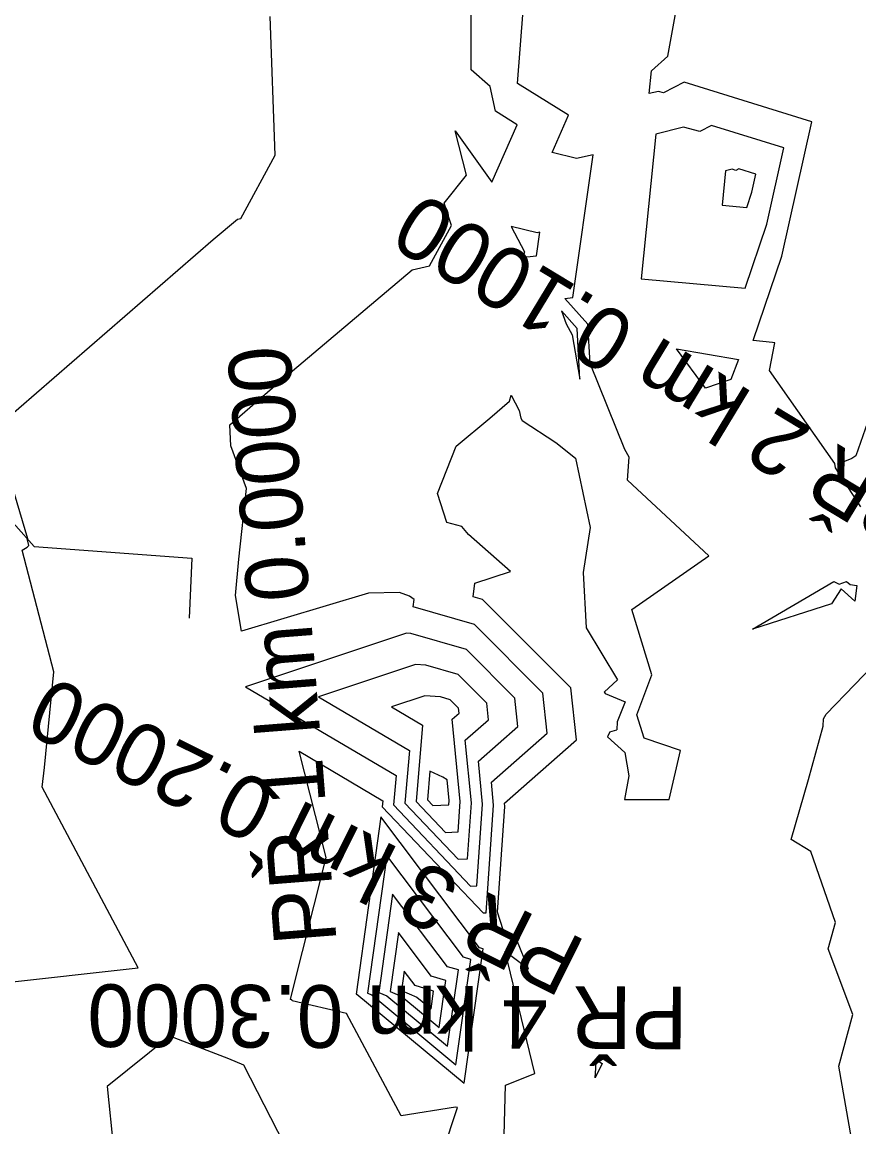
# Model space of a CAD drawing. Extents: x -549394 to -546608, y -1037055 to -1033629.
# Drawn here: x -547520.6 to -547399.4, y -1035351 to -1035190.9 of the extents above; entities that cross this region are included whole.
import ezdxf

# ---------------------------------------------------------------- set-up
doc = ezdxf.new("R2010")
doc.units = 0
for name, color, linetype in [('hlavni_vrst', 7, 'Continuous'), ('hrana_L', 7, 'Continuous'), ('norm_vrst', 7, 'Continuous'), ('x_popis_pricne_rezy_C1', 7, 'Continuous')]:
    doc.layers.add(name, color=color, linetype=linetype)

msp = doc.modelspace()

# ---------------------------------------------------------------- linework, layer by layer
at = {"layer": 'hlavni_vrst'}
for p, q in [((-547483.99, -1035210.2), (-547484.7, -1035190.12)), ((-547488.97, -1035219.38), (-547483.99, -1035210.2)), ((-547489.42, -1035219.48), (-547488.97, -1035219.38)), ((-547492.94, -1035222.45), (-547489.42, -1035219.48)), ((-547523.68, -1035249.07), (-547492.94, -1035222.45)), ((-547519.79, -1035265.79), (-547522.11, -1035257.98)), ((-547519.64, -1035266.74), (-547519.91, -1035265.75)), ((-547519.91, -1035265.75), (-547519.79, -1035265.79)), ((-547520.63, -1035267.42), (-547519.9, -1035266.99)), ((-547516.04, -1035285.05), (-547520.63, -1035267.42)), ((-547519.9, -1035266.99), (-547519.64, -1035266.74)), ((-547464.97, -1035279.47), (-547488.26, -1035287.2)), ((-547464.33, -1035279.51), (-547464.97, -1035279.47)), ((-547456.29, -1035281.82), (-547464.33, -1035279.51)), ((-547449.28, -1035288.85), (-547456.29, -1035281.82)), ((-547517.38, -1035298.89), (-547516.04, -1035285.05)), ((-547516.04, -1035285.05), (-547516.04, -1035285.05)), ((-547516.04, -1035285.05), (-547516.04, -1035285.05)), ((-547516.04, -1035285.05), (-547516.04, -1035285.05)), ((-547516.04, -1035285.05), (-547516.04, -1035285.05)), ((-547488.26, -1035287.2), (-547466.48, -1035300.08)), ((-547448.84, -1035292.96), (-547449.28, -1035288.85)), ((-547454.56, -1035297.99), (-547448.84, -1035292.96)), ((-547517.74, -1035301.73), (-547517.38, -1035298.89)), ((-547453.95, -1035304.2), (-547454.56, -1035297.99)), ((-547466.48, -1035300.08), (-547466.83, -1035304.32)), ((-547503.81, -1035327.94), (-547517.74, -1035301.73)), ((-547454.77, -1035316.04), (-547453.95, -1035304.2)), ((-547466.83, -1035304.32), (-547455.69, -1035316.08)), ((-547467.83, -1035311.63), (-547470.61, -1035331.59)), ((-547456.72, -1035326.39), (-547467.83, -1035311.63)), ((-547455.69, -1035316.08), (-547454.77, -1035316.04)), ((-547455.65, -1035326.7), (-547456.72, -1035326.39)), ((-547524.38, -1035330.2), (-547503.81, -1035327.94)), ((-547457.82, -1035341.95), (-547455.65, -1035326.7)), ((-547470.61, -1035331.59), (-547470, -1035331.85)), ((-547470, -1035331.85), (-547457.82, -1035341.95)), ((-547499.22, -1035337.83), (-547508.31, -1035345.11)), ((-547490.68, -1035341.09), (-547499.22, -1035337.83)), ((-547488.52, -1035342), (-547490.68, -1035341.09)), ((-547482.63, -1035353.51), (-547488.52, -1035342)), ((-547508.31, -1035345.11), (-547507.41, -1035354.07))]:
    msp.add_line(p, q, dxfattribs=at)
at = {"layer": 'hrana_L'}
for p, q in [((-547394.93, -1035239.52), (-547399.91, -1035253.77)), ((-547540.11, -1035243.13), (-547518.88, -1035266.9)), ((-547400.47, -1035254.17), (-547402.61, -1035255)), ((-547399.91, -1035253.77), (-547400.47, -1035254.17)), ((-547518.88, -1035266.9), (-547496.05, -1035268.59)), ((-547496.05, -1035268.59), (-547496.42, -1035277.28))]:
    msp.add_line(p, q, dxfattribs=at)
at = {"layer": 'norm_vrst'}
for p, q in [((-547427.14, -1035195.86), (-547422.74, -1035172.18)), ((-547455.6, -1035197.85), (-547455.58, -1035186.85)), ((-547448.87, -1035199.84), (-547448.06, -1035189.29)), ((-547429.5, -1035198), (-547427.14, -1035195.86)), ((-547452.87, -1035200.27), (-547455.6, -1035197.85)), ((-547429.8, -1035201.29), (-547429.5, -1035198)), ((-547441.49, -1035204.44), (-547448.87, -1035199.84)), ((-547424.77, -1035199.66), (-547427.75, -1035201.2)), ((-547406.29, -1035205.37), (-547424.77, -1035199.66)), ((-547452.09, -1035203.85), (-547452.87, -1035200.27)), ((-547428.49, -1035201), (-547429.8, -1035201.29)), ((-547427.75, -1035201.2), (-547428.49, -1035201)), ((-547448.94, -1035205.81), (-547452.09, -1035203.85)), ((-547443.87, -1035209.85), (-547441.49, -1035204.44)), ((-547452.59, -1035214.12), (-547448.94, -1035205.81)), ((-547424.86, -1035206.17), (-547428.84, -1035207.19)), ((-547422.5, -1035206.81), (-547424.86, -1035206.17)), ((-547420.81, -1035205.94), (-547422.5, -1035206.81)), ((-547410.33, -1035209.17), (-547420.81, -1035205.94)), ((-547410.63, -1035224.86), (-547406.29, -1035205.37)), ((-547457.93, -1035206.68), (-547452.59, -1035214.12)), ((-547456.28, -1035213.14), (-547457.93, -1035206.68)), ((-547428.84, -1035207.19), (-547430.99, -1035228.15)), ((-547412.79, -1035220.23), (-547410.33, -1035209.17)), ((-547440.34, -1035210.71), (-547443.87, -1035209.85)), ((-547440.86, -1035230.85), (-547437.93, -1035210.18)), ((-547437.93, -1035210.18), (-547440.34, -1035210.71)), ((-547418.75, -1035212.51), (-547419.26, -1035217.47)), ((-547417.81, -1035212.27), (-547418.75, -1035212.51)), ((-547417.25, -1035212.42), (-547417.81, -1035212.27)), ((-547416.85, -1035212.21), (-547417.25, -1035212.42)), ((-547414.37, -1035212.98), (-547416.85, -1035212.21)), ((-547414.95, -1035215.6), (-547414.37, -1035212.98)), ((-547459.51, -1035217.16), (-547456.28, -1035213.14)), ((-547415.69, -1035217.78), (-547414.95, -1035215.6)), ((-547458.44, -1035220.39), (-547459.51, -1035217.16)), ((-547419.26, -1035217.47), (-547415.69, -1035217.78)), ((-547461.63, -1035226.27), (-547458.44, -1035220.39)), ((-547449.82, -1035220.54), (-547447.89, -1035224.24)), ((-547446.06, -1035221.45), (-547449.82, -1035220.54)), ((-547415.9, -1035229.47), (-547412.79, -1035220.23)), ((-547446.15, -1035224.81), (-547445.66, -1035221.36)), ((-547445.66, -1035221.36), (-547446.06, -1035221.45)), ((-547447.89, -1035224.24), (-547448.08, -1035224.9)), ((-547448.08, -1035224.9), (-547447.53, -1035224.94)), ((-547447.53, -1035224.94), (-547446.15, -1035224.81)), ((-547414.74, -1035237.07), (-547410.63, -1035224.86)), ((-547483.65, -1035243.3), (-547464.16, -1035226.84)), ((-547464.16, -1035226.84), (-547461.63, -1035226.27)), ((-547430.99, -1035228.15), (-547415.9, -1035229.47)), ((-547442.02, -1035230.96), (-547440.86, -1035230.85)), ((-547438.69, -1035234.71), (-547442.02, -1035230.96)), ((-547442.5, -1035232.79), (-547441.86, -1035234.63)), ((-547440.24, -1035235.34), (-547442.5, -1035232.79)), ((-547441.86, -1035234.63), (-547440.97, -1035236.26)), ((-547439.85, -1035242.68), (-547440.24, -1035235.34)), ((-547438.39, -1035240.39), (-547438.69, -1035234.71)), ((-547440.97, -1035236.26), (-547439.85, -1035242.68)), ((-547421.66, -1035243.97), (-547425.85, -1035238.28)), ((-547425.85, -1035238.28), (-547416.89, -1035239.8)), ((-547411.98, -1035237.37), (-547414.74, -1035237.07)), ((-547412.42, -1035241.42), (-547411.63, -1035237.42)), ((-547411.63, -1035237.42), (-547411.98, -1035237.37)), ((-547416.89, -1035239.8), (-547417.98, -1035242.69)), ((-547433.36, -1035252.86), (-547438.39, -1035240.39)), ((-547402.94, -1035254.86), (-547412.42, -1035241.42)), ((-547490.56, -1035249.29), (-547483.65, -1035243.3)), ((-547417.98, -1035242.69), (-547421.66, -1035243.97)), ((-547450.03, -1035245.86), (-547449.83, -1035244.96)), ((-547449.83, -1035244.96), (-547448.63, -1035247.18)), ((-547452.88, -1035248.29), (-547450.03, -1035245.86)), ((-547448.63, -1035247.18), (-547448.43, -1035248.32)), ((-547490.38, -1035252.33), (-547490.56, -1035249.29)), ((-547457.75, -1035252.36), (-547452.88, -1035248.29)), ((-547448.43, -1035248.32), (-547448.22, -1035248.63)), ((-547448.22, -1035248.63), (-547443.34, -1035251.83)), ((-547488.13, -1035258.5), (-547490.38, -1035252.33)), ((-547460.47, -1035259.23), (-547457.75, -1035252.36)), ((-547443.34, -1035251.83), (-547440.51, -1035254.12)), ((-547432.7, -1035253.95), (-547433.36, -1035252.86)), ((-547440.51, -1035254.12), (-547438.37, -1035264.15)), ((-547432.95, -1035257.28), (-547432.7, -1035253.95)), ((-547402.86, -1035255.5), (-547402.94, -1035254.86)), ((-547399.19, -1035261.16), (-547402.86, -1035255.5)), ((-547421.19, -1035268.25), (-547432.95, -1035257.28)), ((-547489.23, -1035268.75), (-547488.13, -1035258.5)), ((-547459.13, -1035263.43), (-547460.47, -1035259.23)), ((-547456.94, -1035263.99), (-547459.13, -1035263.43)), ((-547455.97, -1035265.15), (-547456.94, -1035263.99)), ((-547438.37, -1035264.15), (-547439.38, -1035270.67)), ((-547449.89, -1035270.5), (-547455.97, -1035265.15)), ((-547489.71, -1035274), (-547489.23, -1035268.75)), ((-547432.32, -1035276.03), (-547421.19, -1035268.25)), ((-547455.08, -1035272.23), (-547449.89, -1035270.5)), ((-547455.3, -1035274.17), (-547455.08, -1035272.23)), ((-547439.38, -1035270.67), (-547438.93, -1035278.69)), ((-547414.86, -1035278.87), (-547403.07, -1035271.98)), ((-547403.07, -1035271.98), (-547402.33, -1035272.33)), ((-547402.33, -1035272.33), (-547401.26, -1035271.97)), ((-547401.26, -1035271.97), (-547400.7, -1035272.4)), ((-547470.47, -1035273.65), (-547488.88, -1035279.14)), ((-547465.99, -1035273.57), (-547470.47, -1035273.65)), ((-547464.53, -1035274.07), (-547465.99, -1035273.57)), ((-547402.04, -1035273.04), (-547403.41, -1035275.22)), ((-547400.06, -1035274.8), (-547402.04, -1035273.04)), ((-547400.7, -1035272.4), (-547399.73, -1035272.53)), ((-547399.73, -1035272.53), (-547400.06, -1035274.8)), ((-547488.88, -1035279.14), (-547489.71, -1035274)), ((-547463.87, -1035274.55), (-547464.53, -1035274.07)), ((-547463.99, -1035275.64), (-547463.87, -1035274.55)), ((-547453.95, -1035274.56), (-547455.3, -1035274.17)), ((-547441.15, -1035287.39), (-547453.95, -1035274.56)), ((-547403.41, -1035275.22), (-547414.86, -1035278.87)), ((-547455.12, -1035278.19), (-547463.99, -1035275.64)), ((-547429.44, -1035285.46), (-547432.32, -1035276.03)), ((-547445.22, -1035288.12), (-547455.12, -1035278.19)), ((-547438.93, -1035278.69), (-547434.43, -1035286.23)), ((-547404.2, -1035291.19), (-547395.97, -1035282.66)), ((-547463.64, -1035284), (-547477.69, -1035288.66)), ((-547462.18, -1035284.1), (-547463.64, -1035284)), ((-547457.47, -1035285.45), (-547462.18, -1035284.1)), ((-547453.35, -1035289.58), (-547457.47, -1035285.45)), ((-547434.43, -1035286.23), (-547436.33, -1035288)), ((-547431.59, -1035291.29), (-547429.44, -1035285.46)), ((-547444.59, -1035293.94), (-547445.22, -1035288.12)), ((-547440.34, -1035294.91), (-547441.15, -1035287.39)), ((-547436.33, -1035288), (-547436.27, -1035288.03)), ((-547436.27, -1035288.03), (-547436.19, -1035288.2)), ((-547436.19, -1035288.2), (-547433.28, -1035289.38)), ((-547477.69, -1035288.66), (-547464.55, -1035296.43)), ((-547462.32, -1035288.53), (-547467.13, -1035290.13)), ((-547460.03, -1035288.68), (-547462.32, -1035288.53)), ((-547458.64, -1035289.09), (-547460.03, -1035288.68)), ((-547457.42, -1035290.3), (-547458.64, -1035289.09)), ((-547453.09, -1035291.99), (-547453.35, -1035289.58)), ((-547433.28, -1035289.38), (-547434.45, -1035292.28)), ((-547467.13, -1035290.13), (-547462.63, -1035292.79)), ((-547458.34, -1035291.89), (-547457.34, -1035291.02)), ((-547457.34, -1035291.02), (-547457.42, -1035290.3)), ((-547430.55, -1035294.64), (-547431.59, -1035291.29)), ((-547404.6, -1035291.85), (-547404.2, -1035291.19)), ((-547462.63, -1035292.79), (-547463.56, -1035303.82)), ((-547457.17, -1035303.85), (-547458.34, -1035291.89)), ((-547456.45, -1035294.94), (-547453.09, -1035291.99)), ((-547434.45, -1035292.28), (-547434.5, -1035293.43)), ((-547406.73, -1035300.62), (-547404.64, -1035292.94)), ((-547404.64, -1035292.94), (-547404.6, -1035291.85)), ((-547452.67, -1035301.04), (-547444.59, -1035293.94)), ((-547435.54, -1035293.74), (-547435.86, -1035294.48)), ((-547435.86, -1035294.48), (-547433.33, -1035296.72)), ((-547435.54, -1035293.74), (-547434.5, -1035293.43)), ((-547455.56, -1035304.02), (-547456.45, -1035294.94)), ((-547450.78, -1035304.09), (-547440.34, -1035294.91)), ((-547425.27, -1035296.42), (-547430.55, -1035294.64)), ((-547476.61, -1035311.95), (-547480.53, -1035296.55)), ((-547480.53, -1035296.55), (-547468.4, -1035303.73)), ((-547464.55, -1035296.43), (-547465.2, -1035304.07)), ((-547433.33, -1035296.72), (-547432.75, -1035300.09)), ((-547426.92, -1035303.53), (-547425.27, -1035296.42)), ((-547461.58, -1035299.42), (-547461.93, -1035303.57)), ((-547459.72, -1035300.31), (-547461.58, -1035299.42)), ((-547459.07, -1035300.69), (-547459.72, -1035300.31)), ((-547458.78, -1035303.67), (-547459.07, -1035300.69)), ((-547432.75, -1035300.09), (-547433.38, -1035303.53)), ((-547409.24, -1035309.35), (-547406.73, -1035300.62)), ((-547452.35, -1035304.38), (-547452.67, -1035301.04)), ((-547468.4, -1035303.73), (-547468.47, -1035304.58)), ((-547465.2, -1035304.07), (-547457.5, -1035312.19)), ((-547463.56, -1035303.82), (-547459.32, -1035308.3)), ((-547461.93, -1035303.57), (-547461.13, -1035304.41)), ((-547458.82, -1035304.31), (-547458.78, -1035303.67)), ((-547457.47, -1035308.22), (-547457.17, -1035303.85)), ((-547456.12, -1035312.13), (-547455.56, -1035304.02)), ((-547450.74, -1035304.55), (-547450.78, -1035304.09)), ((-547433.38, -1035303.53), (-547426.92, -1035303.53)), ((-547468.47, -1035304.58), (-547453.87, -1035319.97)), ((-547461.13, -1035304.41), (-547458.82, -1035304.31)), ((-547453.42, -1035319.95), (-547452.35, -1035304.38)), ((-547451.8, -1035319.88), (-547450.74, -1035304.55)), ((-547468.67, -1035306.04), (-547472.25, -1035331.71)), ((-547454.38, -1035325.02), (-547468.67, -1035306.04)), ((-547459.32, -1035308.3), (-547457.47, -1035308.22)), ((-547406.39, -1035311.07), (-547409.24, -1035309.35)), ((-547481.74, -1035332.47), (-547476.61, -1035311.95)), ((-547457.5, -1035312.19), (-547456.12, -1035312.13)), ((-547402.86, -1035321.34), (-547406.39, -1035311.07)), ((-547466.98, -1035317.23), (-547468.97, -1035331.47)), ((-547459.05, -1035327.76), (-547466.98, -1035317.23)), ((-547453.87, -1035319.97), (-547453.42, -1035319.95)), ((-547450.95, -1035322.43), (-547451.8, -1035319.88)), ((-547403.9, -1035325.15), (-547402.86, -1035321.34)), ((-547466.14, -1035322.82), (-547467.33, -1035331.34)), ((-547461.39, -1035329.12), (-547466.14, -1035322.82)), ((-547449.01, -1035323.9), (-547450.95, -1035322.43)), ((-547453.86, -1035325.17), (-547454.38, -1035325.02)), ((-547447.29, -1035328.06), (-547449.01, -1035323.9)), ((-547456.62, -1035344.64), (-547453.86, -1035325.17)), ((-547446.39, -1035343.2), (-547450.67, -1035325.49)), ((-547450.67, -1035325.49), (-547447.29, -1035328.06)), ((-547400.32, -1035334.67), (-547403.9, -1035325.15)), ((-547457.45, -1035328.23), (-547459.05, -1035327.76)), ((-547459.01, -1035339.25), (-547457.45, -1035328.23)), ((-547465.29, -1035328.42), (-547465.68, -1035331.22)), ((-547463.73, -1035330.49), (-547465.29, -1035328.42)), ((-547459.25, -1035329.75), (-547461.39, -1035329.12)), ((-547460.21, -1035336.55), (-547459.25, -1035329.75)), ((-547467.33, -1035331.34), (-547465.64, -1035332.05)), ((-547465.68, -1035331.22), (-547463.47, -1035332.15)), ((-547461.04, -1035331.28), (-547463.73, -1035330.49)), ((-547461.41, -1035333.86), (-547461.04, -1035331.28)), ((-547481.83, -1035332.47), (-547481.74, -1035332.47)), ((-547481.58, -1035332.57), (-547481.83, -1035332.47)), ((-547481.52, -1035332.7), (-547481.58, -1035332.57)), ((-547473.66, -1035334.55), (-547481.52, -1035332.7)), ((-547472.25, -1035331.71), (-547472.18, -1035331.74)), ((-547472.18, -1035331.74), (-547456.62, -1035344.64)), ((-547468.97, -1035331.47), (-547467.82, -1035331.95)), ((-547467.82, -1035331.95), (-547459.01, -1035339.25)), ((-547465.64, -1035332.05), (-547460.21, -1035336.55)), ((-547463.47, -1035332.15), (-547461.41, -1035333.86)), ((-547465.76, -1035349.35), (-547473.66, -1035334.55)), ((-547402.34, -1035342.16), (-547400.32, -1035334.67)), ((-547436.65, -1035341.77), (-547437.66, -1035343.87)), ((-547437.66, -1035343.87), (-547437.55, -1035342.43)), ((-547437.55, -1035342.43), (-547437.52, -1035341.54)), ((-547437.52, -1035341.54), (-547437.29, -1035341.44)), ((-547437.29, -1035341.44), (-547437.24, -1035341.39)), ((-547437.24, -1035341.39), (-547436.65, -1035341.77)), ((-547399.54, -1035358.21), (-547402.34, -1035342.16)), ((-547450.65, -1035344.91), (-547446.39, -1035343.2)), ((-547450.84, -1035352.14), (-547450.65, -1035344.91)), ((-547457.88, -1035348.08), (-547465.76, -1035349.35)), ((-547462.35, -1035362.55), (-547457.6, -1035348.14)), ((-547457.6, -1035348.14), (-547457.88, -1035348.08))]:
    msp.add_line(p, q, dxfattribs=at)

# ---------------------------------------------------------------- texts
at = {"layer": 'x_popis_pricne_rezy_C1'}
for s, rotation, p in [('PŘ 2 km 0.1000', 148.8028, (-547388.67, -1035260.39)), ('PŘ 1 km 0.0000', 94.5085, (-547475.07, -1035324.19)), ('PŘ 3 km 0.2000', 153.6068, (-547438.68, -1035324.15)), ('PŘ 4 km 0.3000', 179.7616, (-547424.26, -1035330.66))]:
    msp.add_text(s, height=9.0627, rotation=rotation, dxfattribs=at).set_placement(p)

doc.saveas('drawing.dxf')
